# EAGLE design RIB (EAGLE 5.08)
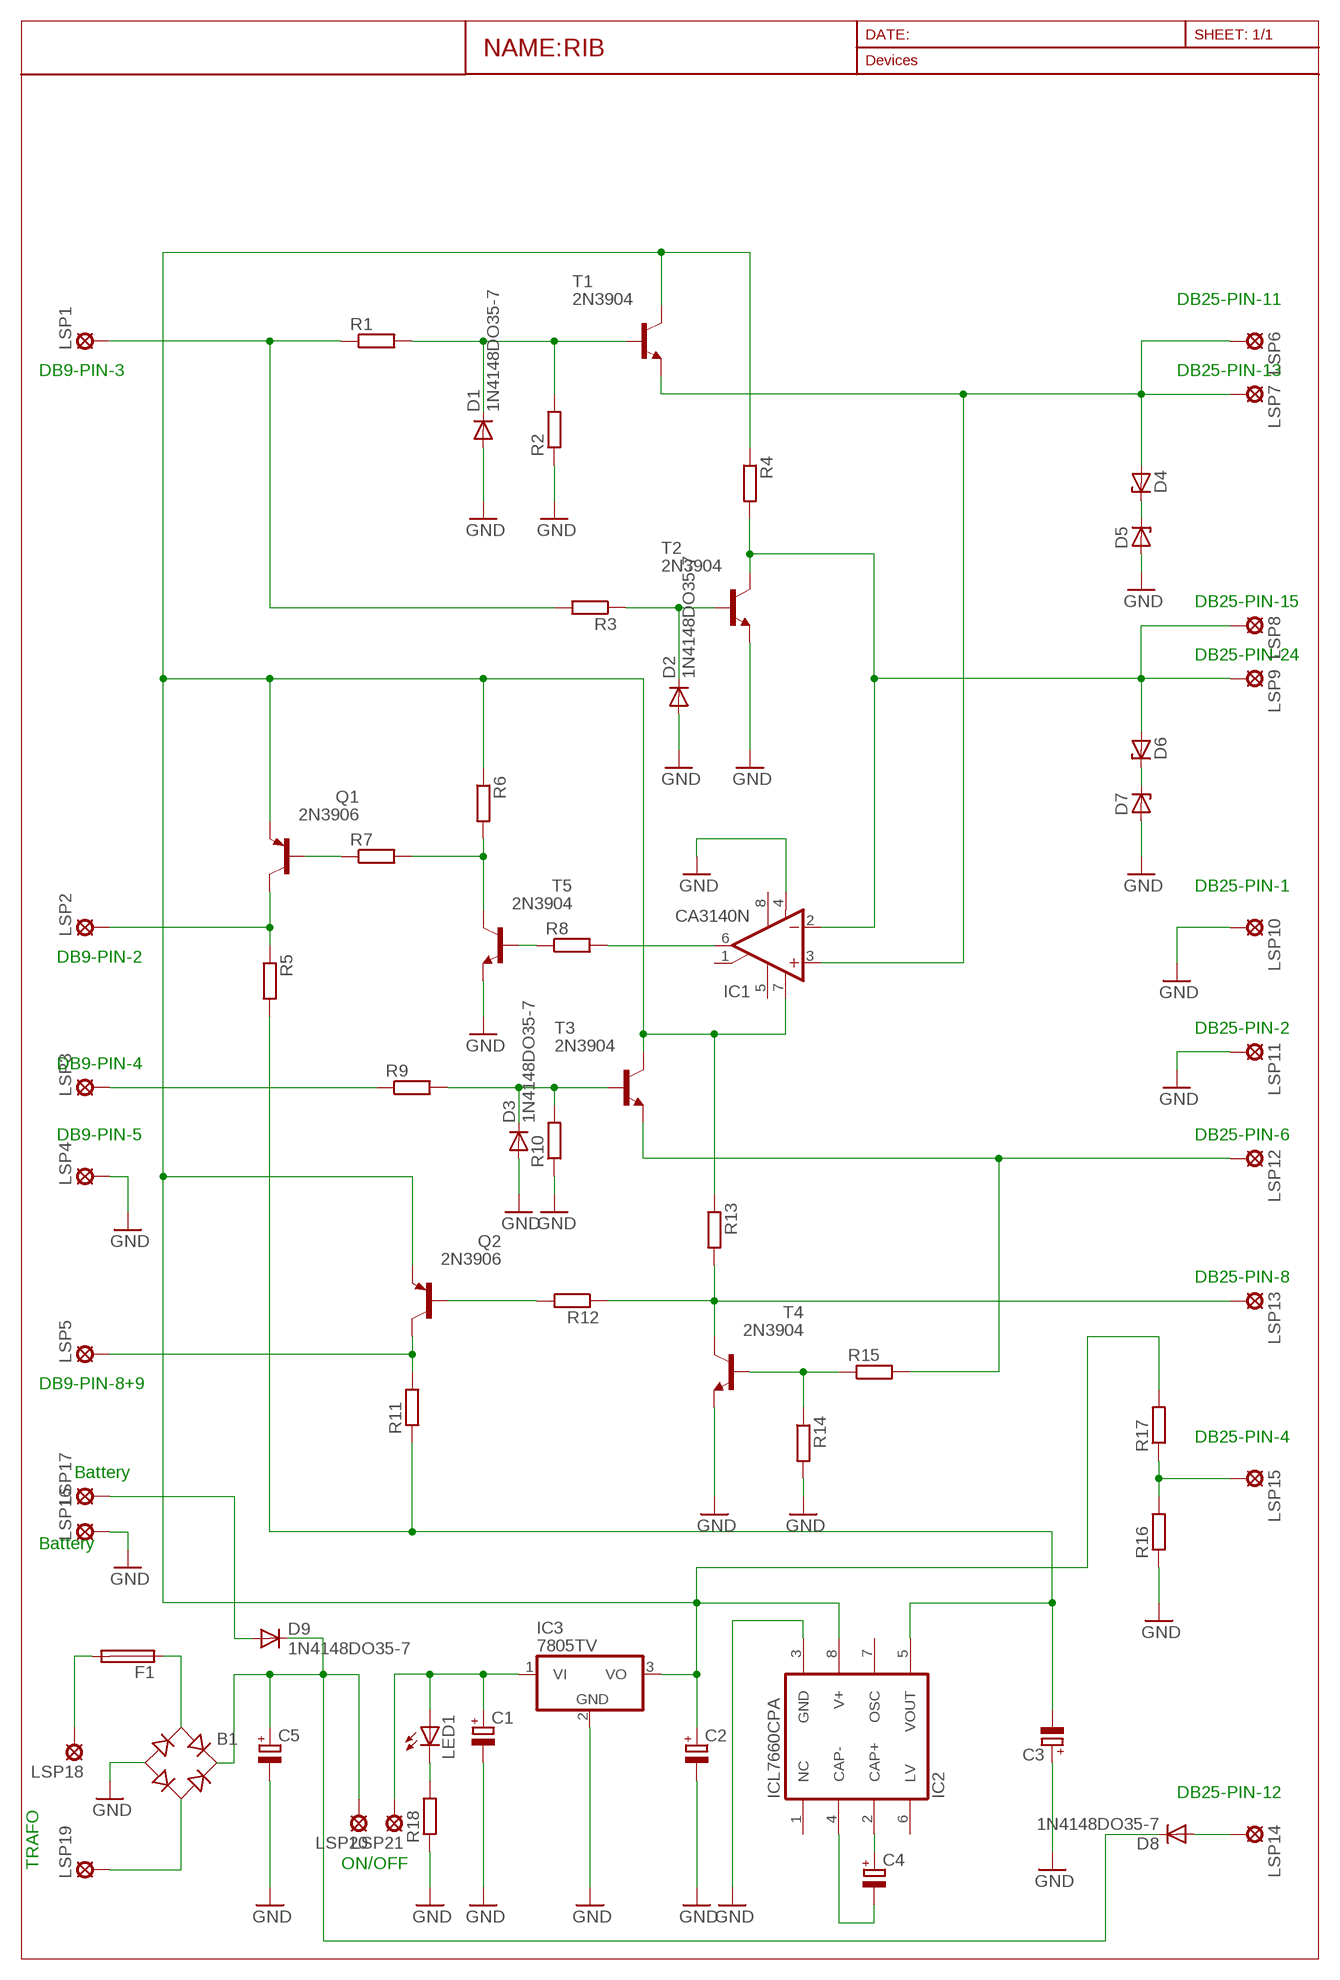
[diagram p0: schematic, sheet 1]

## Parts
B1  RB1A  [RB1A]
C1  CPOL-EUE2.5-6  [E2,5-6]
C2  CPOL-EUE2.5-6  [E2,5-6]
C3  CPOL-EUE2.5-6  [E2,5-6]
C4  CPOL-EUE2.5-6  [E2,5-6]
C5  CPOL-EUE3.5-10  [E3,5-10]
D1  1N4148DO35-7  [DO35-7]
D2  1N4148DO35-7  [DO35-7]
D3  1N4148DO35-7  [DO35-7]
D4  ZENER-DIODEZD-5  [ZDIO-5]
D5  ZENER-DIODEZD-5  [ZDIO-5]
D6  ZENER-DIODEZD-5  [ZDIO-5]
D7  ZENER-DIODEZD-5  [ZDIO-5]
D8  1N4148DO35-7  [DO35-7]
D9  1N4148DO35-7  [DO35-7]
F1  SH25  [SH25]
IC1  CA3140N  [DIL08]
IC2  ICL7660CPA  [DIL08]
IC3  7805TV  [TO220V]
LED1  LED5MM  [LED5MM]
LSP1  SE14  [SE14]
LSP2  SE14  [SE14]
LSP3  SE14  [SE14]
LSP4  SE14  [SE14]
LSP5  SE14  [SE14]
LSP6  SE14  [SE14]
LSP7  SE14  [SE14]
LSP8  SE14  [SE14]
LSP9  SE14  [SE14]
LSP10  SE14  [SE14]
LSP11  SE14  [SE14]
LSP12  SE14  [SE14]
LSP13  SE14  [SE14]
LSP14  SE14  [SE14]
LSP15  SE14  [SE14]
LSP16  SE14  [SE14]
LSP17  SE14  [SE14]
LSP18  SE14  [SE14]
LSP19  SE14  [SE14]
LSP20  SE14  [SE14]
LSP21  SE14  [SE14]
Q1  2N3906  [TO92]
Q2  2N3906  [TO92]
R1  R-EU_0204/7  [0204/7]
R2  R-EU_0204/7  [0204/7]
R3  R-EU_0204/7  [0204/7]
R4  R-EU_0204/7  [0204/7]
R5  R-EU_0204/7  [0204/7]
R6  R-EU_0204/7  [0204/7]
R7  R-EU_0204/7  [0204/7]
R8  R-EU_0204/7  [0204/7]
R9  R-EU_0204/7  [0204/7]
R10  R-EU_0204/7  [0204/7]
R11  R-EU_0204/7  [0204/7]
R12  R-EU_0204/7  [0204/7]
R13  R-EU_0204/7  [0204/7]
R14  R-EU_0204/7  [0204/7]
R15  R-EU_0204/7  [0204/7]
R16  R-EU_0204/7  [0204/7]
R17  R-EU_0204/7  [0204/7]
R18  R-EU_0204/7  [0204/7]
T1  2N3904  [TO92]
T2  2N3904  [TO92]
T3  2N3904  [TO92]
T4  2N3904  [TO92]
T5  2N3904  [TO92]

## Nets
GND: B1.- C1.- C2.- C3.+ C5.- D1.A D2.A D3.A D5.A D7.A IC1.4(V-) IC2.3(GND) IC3.2(GND) LSP4.MP LSP10.MP LSP11.MP LSP16.MP R2.1 R10.1 R14.2 R16.1 R18.1 T2.3(E) T4.3(E) T5.3(E)
N$1: D1.C R1.2 R2.2 T1.2(B)
N$2: D2.C R3.1 T2.2(B)
N$3: LSP3.MP R9.1
N$4: D4.C D5.C
N$5: D6.C D7.C
N$6: IC1.6(OUT) R8.2
N$7: R8.1 T5.2(B)
N$8: R6.2 R7.2 T5.1(C)
N$9: LSP2.MP Q1.1(C) R5.1
N$10: LSP1.MP R1.1 R3.2
N$11: D3.C R9.2 R10.2 T3.2(B)
N$12: LSP13.MP R12.1 R13.2 T4.1(C)
N$13: Q2.2(B) R12.2
N$14: LSP5.MP Q2.1(C) R11.2
N$15: R14.1 R15.1 T4.2(B)
N$16: LSP15.MP R16.2 R17.1
N$17: B1.+ C5.+ D8.C D9.C LSP20.MP
N$18: C2.+ IC1.7(V+) IC2.8(V+) IC3.3(VO) Q1.3(E) Q2.3(E) R4.1 R6.1 R13.1 R17.2 T1.1(C) T3.1(C)
N$19: C3.- IC2.5(VOUT) R5.2 R11.1
N$20: LSP12.MP R15.2 T3.3(E)
N$21: C4.+ IC2.2(CAP+)
N$22: C4.- IC2.4(CAP-)
N$23: F1.2 LSP18.MP
N$24: B1.AC2 LSP19.MP
N$25: D4.A IC1.3(+IN) LSP6.MP LSP7.MP T1.3(E)
N$26: D6.A IC1.2(-IN) LSP8.MP LSP9.MP R4.2 T2.1(C)
N$27: B1.AC1 F1.1
N$28: D8.A LSP14.MP
N$29: LED1.K(C) R18.2
N$30: Q1.2(B) R7.1
N$53: D9.A LSP17.MP
N$54: C1.+ IC3.1(VI) LED1.A LSP21.MP
Unconnected: IC1.1(ON/CMP) IC1.5(ON) IC1.8(CMP) IC2.1(NC) IC2.6(LV) IC2.7(OSC)

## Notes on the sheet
- DB25-PIN-11
- DB9-PIN-3 | DB25-PIN-13
- DB25-PIN-15
- DB25-PIN-24
- DB25-PIN-1
- DB9-PIN-2
- DB25-PIN-2
- DB9-PIN-4
- DB9-PIN-5 | DB25-PIN-6
- DB25-PIN-8
- DB9-PIN-8+9
- DB25-PIN-4
- Battery
- Battery
- DB25-PIN-12
- TRAFO | ON/OFF

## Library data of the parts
B1 = rectifier:RB1A: RECTIFIER 1 A
C1-C5 = rcl:CPOL-EU: POLARIZED CAPACITOR, European symbol
D1-D3 D8 D9 = diode:1N4148: DIODE
D4-D7 = diode:ZENER-DIODE: Z-Diode
F1 = fuse:SH25: FUSE HOLDER
IC1 = linear:CA3140: OP AMP
IC2 = maxim:ICL7660CPA: VOLTAGE CONVERTER
IC3 = linear:78*: Positive VOLTAGE REGULATOR Source: http://cache.national.com/ds/LM/LM78L05.pdf http://www.fairchildsemi.com/ds/LM/LM7805.pdf
LED1 = led:LED: LED
LSP1-LSP21 = solpad:SE14: SOLDER PAD
Q1 Q2 = transistor-pnp:2N3906: PNP Transistor
R1-R18 = rcl:R-EU_: RESISTOR, European symbol
T1-T5 = transistor:2N3904: NPN TRANSISTOR

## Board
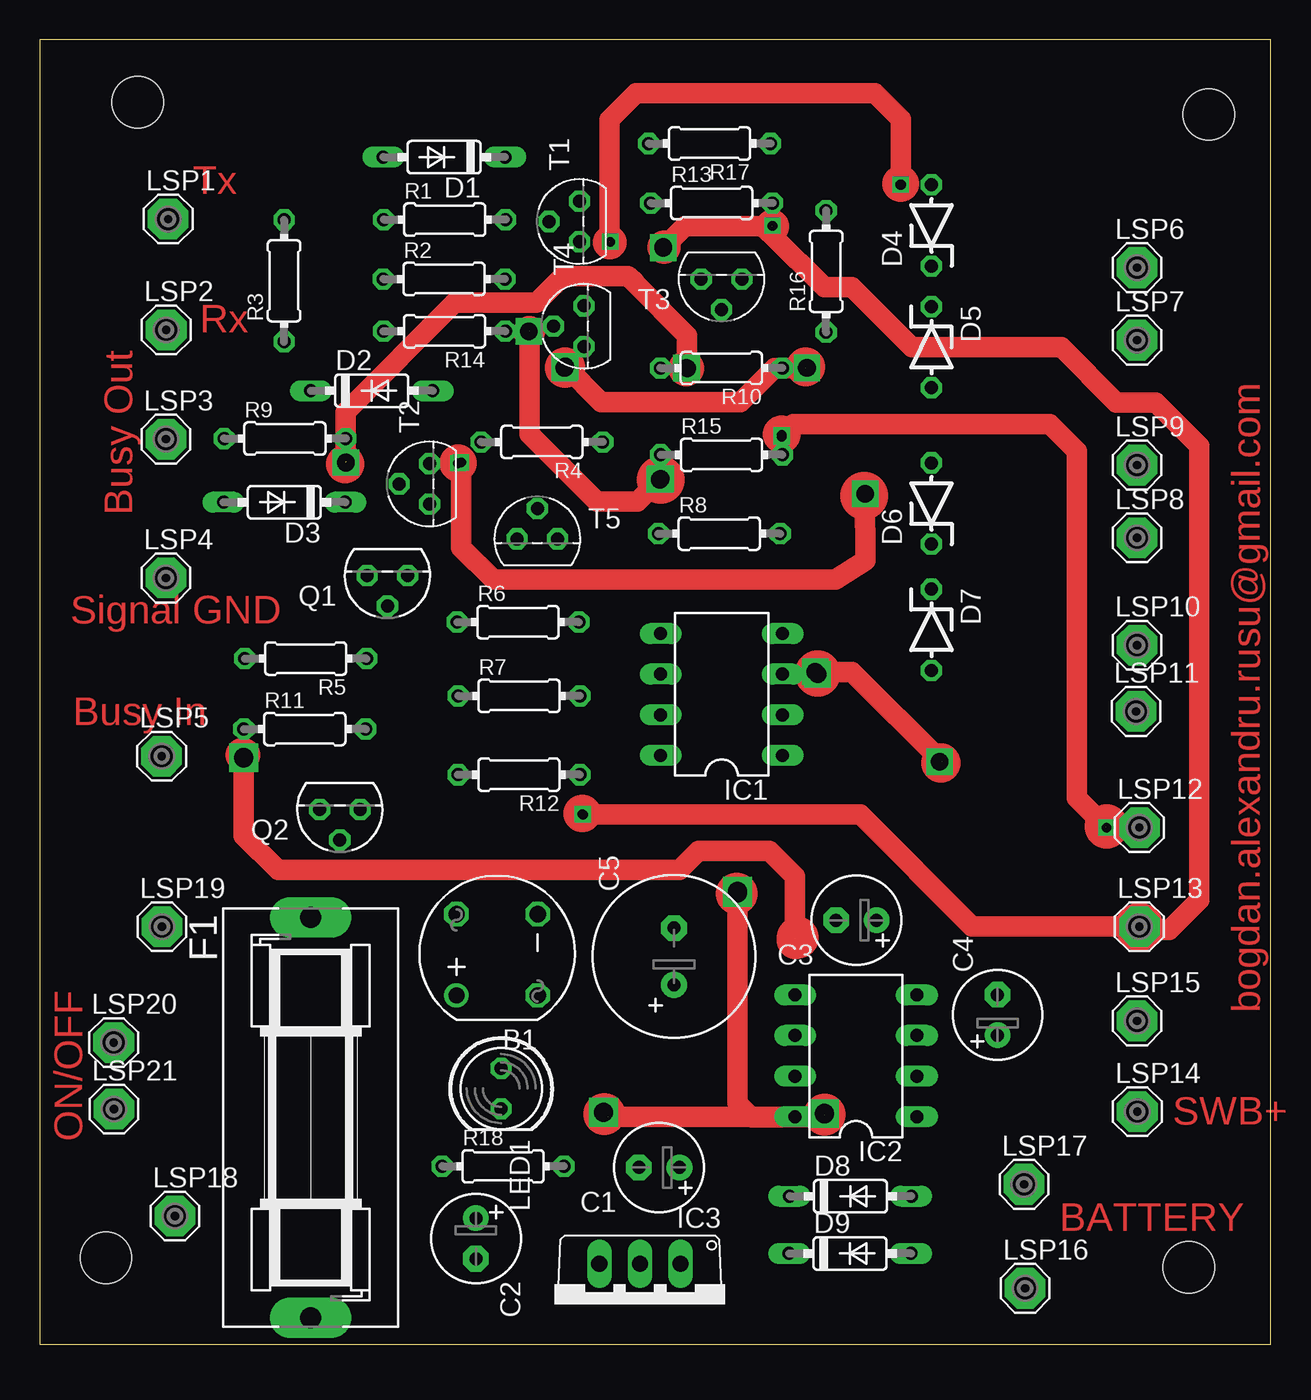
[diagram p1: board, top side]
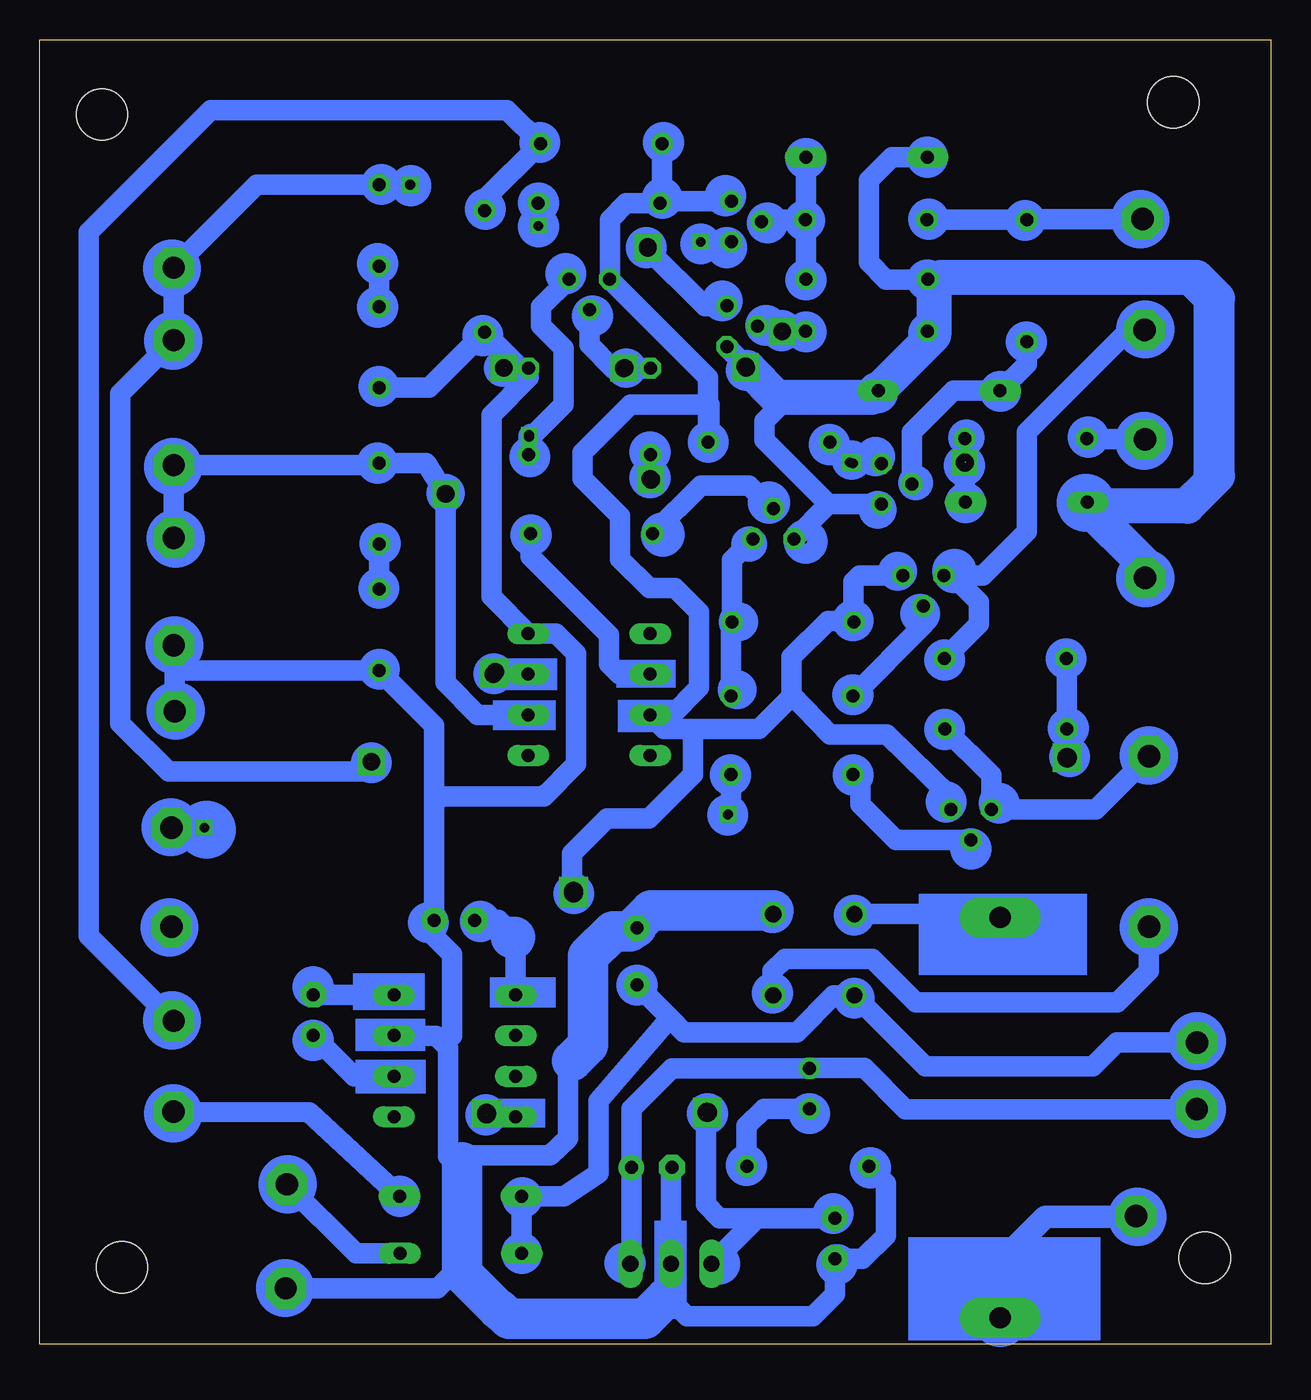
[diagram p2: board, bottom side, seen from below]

Size 76.99 x 81.59 mm. Coordinates in mm from the lower left corner, seen from the top.
Outline: 0,0 76.99,0 76.99,81.59 0,81.59 0,0
Copper layers (1*16): Top 0.035mm / dielectric 1.5mm / Bottom 0.035mm
Design rules "default": minimum track width 10mil, minimum drill 24mil, track to track 8mil, track to pad 8mil, pad to pad 8mil, via to via 8mil, smd to smd 8mil, copper to edge 40mil, drill to drill 8mil, minimum pad ring 10mil, minimum via ring 8mil, stop-mask expansion 4mil, vias tented up to drill 0mil, thermal gap 10mil
Holes 3.2 mm at 6.11,77.69 71.86,4.82 4.13,5.41 73.12,76.93

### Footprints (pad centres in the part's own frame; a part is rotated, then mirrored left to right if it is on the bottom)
RB1A = drill 1.016 round: + -2.54,2.54 | drill 1.016 octagon: - 2.54,-2.54; AC1 2.54,2.54; AC2 -2.54,-2.54
E2,5-6 = drill 0.813 pad 1.6 round: + -1.27,0 | drill 0.813 pad 1.6 octagon: - 1.27,0
E3,5-10 = drill 0.813 pad 1.6 round: + -1.778,0 | drill 0.813 pad 1.6 octagon: - 1.778,0
DO35-7 = drill 0.813 long: A 3.81,0; C -3.81,0
ZDIO-5 = drill 0.813 octagon: A 2.54,0; C -2.54,0
SH25 = drill 1.321 pad 2.54 long: 1 -12.522,0; 2 12.522,0
DIL08 = drill 0.813 long: 1 -3.81,-3.81; 2 -1.27,-3.81; 3 1.27,-3.81; 4 3.81,-3.81; 5 3.81,3.81; 6 1.27,3.81; 7 -1.27,3.81; 8 -3.81,3.81
TO220V = drill 1.016 long: 1 -2.54,-2.54; 2 0,-2.54; 3 2.54,-2.54
LED5MM = drill 0.813 octagon: A -1.27,0; K 1.27,0
SE14 = drill 1.397 pad 2.54 octagon: MP 0,0
TO92 = drill 0.813 octagon: 1 1.27,0; 2 0,1.905; 3 -1.27,0
0204/7 = drill 0.813 octagon: 1 -3.81,0; 2 3.81,0

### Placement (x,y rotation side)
B1  28.6,24.37 90 top
C1  38.73,11.06 180 top
C2  27.27,6.62 270 top
C3  51.07,26.53 180 top
C4  59.9,20.6 90 top
C5  39.66,24.26 90 top
D1  25.28,74.26 180 top
D2  20.75,59.65 0 top
D3  15.29,52.67 180 top
D4  55.77,69.99 90 top
D5  55.77,62.37 270 top
D6  55.77,52.6 90 top
D7  55.77,44.69 270 top
D8  50.7,9.26 0 top
D9  50.67,5.68 0 top
F1  16.93,14.19 270 top
IC1  42.64,40.65 90 top
IC2  51.04,18.04 90 top
IC3  37.53,2.49 180 top
LED1  28.85,16 270 top
LSP1  8.01,70.39 0 top
LSP2  7.9,63.46 0 top
LSP3  7.88,56.62 0 top
LSP4  7.88,47.94 0 top
LSP5  7.61,36.79 0 top
LSP6  68.63,67.35 0 top
LSP7  68.63,62.82 0 top
LSP8  68.63,50.45 0 top
LSP9  68.63,54.99 0 top
LSP10  68.63,43.73 0 top
LSP11  68.56,39.59 0 top
LSP12  68.77,32.32 0 top
LSP13  68.77,26.13 0 top
LSP14  68.64,14.55 0 top
LSP15  68.63,20.23 0 top
LSP16  61.63,3.5 0 top
LSP17  61.55,10.01 0 top
LSP18  8.44,8.02 0 top
LSP19  7.63,26.12 0 top
LSP20  4.61,18.88 0 top
LSP21  4.63,14.71 0 top
Q1  21.73,48.09 180 top
Q2  18.76,33.46 180 top
R1  25.32,70.35 0 top
R2  25.27,66.64 0 top
R3  15.27,66.52 90 top
R4  31.39,56.44 180 top
R5  16.62,42.89 180 top
R6  29.9,45.17 0 top
R7  29.97,40.56 0 top
R8  42.49,50.71 0 top
R9  15.32,56.66 0 top
R10  42.62,61.07 180 top
R11  16.57,38.49 0 top
R12  29.96,35.63 180 top
R13  42.01,71.39 0 top
R14  25.3,63.37 180 top
R15  42.63,55.64 0 top
R16  49.18,67.11 90 top
R17  41.88,75.11 180 top
R18  28.97,11.13 0 top
T1  33.76,70.24 90 top
T2  24.37,53.82 90 top
T3  42.63,66.64 180 top
T4  34.03,63.69 90 top
T5  31.11,50.38 0 top

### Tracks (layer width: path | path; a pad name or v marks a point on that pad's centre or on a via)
GND  (via drill 1.1)  (1 unrouted)
  Top 1.27: v32.86,61.17 35.1,58.94 43.83,58.94 45.96,61.07 47.87,61.07
  Bottom 1.27: R18.1 24.09,10.07 24.09,6.8 25.54,5.35 C2.- 27.27,3.14 28.66,1.75 36.51,1.75 37.58,2.83 | LSP4.MP 7.88,49.07 D3.A 5.69,52.67 4.2,54.16 4.2,65.25 5.63,66.69 21.41,66.69 R2.1 | 27.67,52.55 T5.3 | 27.67,52.55 T2.3 | 68.56,42.04 LSP11.MP | 68.56,42.04 68.56,43.67 LSP10.MP | D1.A 23.71,74.26 25.14,72.83 25.14,67.68 24.07,66.6 21.5,66.6 R2.1 | R2.1 21.47,63.4 R14.2 21.49,62.72 D2.A | D2.A 31.26,59.65 T4.3 34.03,62.34 v32.86,61.17 | D5.A 52.65,59.83 R16.1 46.94,61.07 R10.1 | R10.1 46.43,60.45 48.76,58.13 48.76,46.76 IC1.4 44.71,44.46 43.46,43.21 43.46,36.3 45.48,34.28 | 68.56,42.04 68.45,42.15 D7.A 52.34,38.72 52.34,33.85 | 52.34,33.85 C3.+ 52.34,25.52 51.22,24.4 51.22,19.28 51.72,18.78 | D2.A 29.78,59.65 31.67,57.76 31.67,56.55 27.67,52.55 | 45.48,34.28 51.9,34.28 52.34,33.85 | R10.1 47.87,61.07 47.92,61.01 | C1.- 37.53,11.06 IC3.2 37.58,4.98 37.58,2.83 | B1.- 38.79,26.91 C5.- 41.21,26.04 42.73,24.52 42.73,18.42 43.95,17.12 43.95,12.89 45.09,11.83 50.57,11.83 51.06,11.34 | 45.48,34.28 45.48,34.38 | LSP16.MP 52.12,3.5 51.22,4.4 | 51.22,4.4 51.06,4.56 51.06,11.34 | 51.06,11.34 51.47,11.76 51.47,18.53 51.72,18.78 | 51.72,18.78 52.21,19.28 54.82,19.28 IC2.3 | 37.58,2.83 37.58,2.33 38.25,1.67 48.49,1.67 51.22,4.4
N$1
  Bottom 1.27: D1.C 29.09,70.38 R1.2 | R1.2 31.74,70.35 T1.2 | R2.2 29.09,70.31 R1.2
N$2
  Bottom 1.27: R3.1 15.27,61.32 D2.C 19.87,59.65 22.46,57.06 T2.2
N$3
  Bottom 1.27: LSP3.MP 11.47,56.62 R9.1
N$4
  Bottom 1.27: D4.C D5.C
N$5
  Bottom 1.27: D7.C D6.C | D7.C
N$6
  Bottom 1.27: IC1.6 40.78,41.92 41.41,42.55 41.41,44.38 46.31,49.29 46.31,50.69 R8.2
N$7
  Bottom 1.27: R8.1 35.66,53.73 32.66,53.73 31.21,52.29 T5.2
N$8
  Bottom 1.27: T5.1 33.71,49.05 R6.2 33.78,45.11 R7.2
N$9
  Bottom 1.27: R5.1 18.27,45.05 18.27,46.43 19.93,48.09 Q1.1 18.01,48.09 15.27,50.83 15.27,57.05 9.15,63.17 8.18,63.17 LSP2.MP
N$10
  Bottom 1.27: LSP1.MP 15.22,70.39 R3.2 21.49,70.33 R1.1
N$11  (via drill 1.1)  (1 unrouted)
  Top 1.27: v40.48,61.05 40.48,63.1 37.21,66.37 37.21,66.41 36.79,66.83 32.73,66.83 31.05,65.15 25.94,65.15 19.11,58.32 19.11,55.18 19.07,55.14
  Bottom 1.27: R9.2 19.13,52.71 D3.C | T3.2 42.63,62.52 41.14,61.03 38.85,61.03 R10.2 | R9.2 19.13,55.22 19.19,55.16 | R10.2 40.05,61.07 40.15,60.96 | R9.2 19.07,56.6 19.07,55.06 | R10.2 38.83,61.05 v40.48,61.05
N$12  (via drill 0.6, 1.1)  (1 unrouted)
  Top 1.27: v33.97,33.13 51.31,33.13 58.3,26.15 68.21,26.15 | 68.21,26.15 68.75,26.15 LSP13.MP | 68.21,26.15 68.42,25.93 70.65,25.93 72.52,27.8 72.52,56.18 69.78,58.91 67.34,58.91 63.89,62.37 54.54,62.37 50.8,66.12 49.07,66.12 45.8,69.39 45.8,69.93 40.34,69.93 v38.98,68.57
  Bottom 1.27: R13.2 45.8,71.37 45.8,69.93 | T4.1 34.06,64.93 35.41,64.93 38.98,68.5 v38.98,68.57 | R12.1 33.77,33.33 v33.97,33.13
N$13
  Bottom 1.27: Q2.2 23.46,31.55 25.68,33.77 25.68,35.93 R12.2
N$14
  Bottom 1.27: LSP5.MP 10.94,33.46 Q2.1 17.49,35.6 R11.2
N$15  (via drill 1.1)  (1 unrouted)
  Top 1.27: v38.77,54.09 37.39,52.71 34.83,52.71 30.62,56.92 30.62,63.37
  Bottom 1.27: R14.1 30.62,63.37 | T4.2 31.81,63.37 30.62,63.37 | 30.62,63.37 30.58,63.41 | R15.1 38.82,54.14 v38.77,54.09
N$16
  Bottom 1.27: LSP15.MP 73.96,25.56 73.96,69.57 66.33,77.21 47.78,77.21 45.69,75.12 R17.1 49.18,71.63 R16.2
N$17
  Bottom 1.27: LSP20.MP 9.64,18.88 11.14,17.38 21.61,17.38 B1.+ 27.35,21.83 29.65,19.53 36.7,19.53 37.6,20.42 | 37.6,20.42 C5.+ | D9.C 46.86,9.24 D8.C 44.21,9.26 42.06,10.68 42.06,15.23 37.6,20.42
N$18  (via drill 1.2)  (2 unrouted)
  Top 1.27: v43.62,28.34 43.62,15.08 44.52,14.19 48.91,14.19 49.07,14.35 | IC2.8 35.54,14.23 35.26,14.52
  Bottom 1.27: C2.+ 32.13,7.89 | 32.13,7.89 IC3.3 | T1.1 38.09,71.51 R13.1 | R17.2 38.07,71.52 R13.1 | R13.1 40.32,71.39 41.35,70.36 T3.1 35.2,60.48 R4.1 35.12,56.52 35.12,58.77 40.06,58.77 43.07,55.77 43.07,54.16 40.71,51.8 40.71,49.12 38.88,47.29 37.27,47.29 35.77,45.79 35.77,41.07 37.59,39.25 37.59,38.49 | Q1.3 25.74,48.09 26.11,47.72 26.11,45.19 R6.1 26.17,45.25 27.72,45.25 29.97,43 29.97,40.64 | Q2.3 20.03,34.24 24.03,38.15 27.57,38.15 29.97,40.64 | IC1.7 37.95,38.49 37.59,38.49 | 36.16,38.49 32.01,38.49 29.97,40.53 29.97,40.64 | 36.16,38.49 37.59,38.49 | 36.16,38.49 36.15,38.5 36.15,35.65 38.91,32.89 41.51,32.89 43.71,30.7 43.71,28.42 v43.62,28.34 | IC2.8 48.95,14.23 49.07,14.35 | 32.13,7.89 34.48,7.89 35.34,8.74 35.34,14.03 35.54,14.23
N$19  (via drill 1.2)  (1 unrouted)
  Top 1.27: v12.74,36.69 12.74,31.81 14.89,29.66 39.99,29.66 41.19,30.85 45.63,30.85 47.21,29.28 47.21,25.42 47.23,25.4
  Bottom 1.27: IC2.5 47.23,25.47 48.31,26.54 49.79,26.54 C3.- | R5.2 12.76,42.84 R11.1 v12.76,36.7 v12.74,36.69
N$20  (via drill 0.6)  (1 unrouted)
  Top 1.27: v46.4,56.77 46.4,56.82 47.15,57.57 63.18,57.57 64.87,55.88 64.87,34.16 66.67,32.37
  Bottom 1.27: T3.3 45.64,64.89 45.64,63.71 44.25,62.31 44.25,58.77 46.44,56.58 R15.2 | R15.2 46.44,56.83 46.35,56.92 | LSP12.MP 66.71,32.32 66.67,32.37 | R15.2 46.44,56.73 v46.4,56.77
N$21
  Bottom 1.27: IC2.2 57.34,16.77 C4.+
N$22
  Bottom 1.27: IC2.4 59.88,21.85 C4.-
N$23
  Bottom 1.422: F1.2 16.93,5.15 14.11,7.97 8.49,7.97 LSP18.MP
N$24
  Bottom 1.27: LSP19.MP 7.63,23.37 9.61,21.39 22.19,21.39 24.93,24.12 30.39,24.12 31.17,23.35 31.17,21.86 B1.AC2
N$25  (via drill 0.6, 1.1)  (2 unrouted)
  Top 1.27: v53.86,72.54 53.86,76.63 52.24,78.25 37.29,78.25 35.64,76.6 35.64,68.97 | v48.5,42.06 50.79,42.06 56.41,36.44
  Bottom 1.27: LSP7.MP LSP6.MP 63.44,72.53 D4.A v53.86,72.53 v53.86,72.54 | LSP7.MP | T1.3 35.64,68.97 35.64,68.96 | IC1.3 48.36,41.92 v48.5,42.06 | LSP7.MP 71.97,59.48 71.97,38.85 68.94,35.82 57.04,35.82 arc-90 56.41,36.44 arc90 56.28,36.58
N$26  (via drill 0.6, 1.1)
  Top 1.27: v26.35,55.17 26.35,49.84 28.36,47.82 49.75,47.82 51.63,49.02 51.61,53.12 51.62,53.12 v51.62,53.19
  Bottom 1.27: T2.1 26.23,55.09 R4.2 26.35,55.21 v26.35,55.17 | LSP8.MP LSP9.MP 55.91,54.99 D6.A 55.75,55.12 52.83,55.12 v51.62,53.19 51.62,52.97 51.62,41.39 49.61,39.38 IC1.2
N$27
  Bottom 0.406: F1.1 21.73,26.71 21.73,26.91
  Bottom 1.27: 21.73,26.91 B1.AC1
N$28
  Bottom 1.27: LSP14.MP 60.15,14.5 D8.A
N$29
  Bottom 1.27: LED1.K 31.72,14.73 32.79,13.66 32.79,11.15 R18.2
N$30
  Bottom 1.27: Q1.2 21.73,44.99 R7.1
N$31  (via drill 1.2)
  other vias: 43.62,28.26
N$32  (via drill 1.2)
  other vias: 35.26,14.52
N$33  (via drill 0.6)
  other vias: 12.77,36.93
N$34  (via drill 0.6)
  other vias: 33.93,33.16
N$35  (via drill 0.6)
  other vias: 35.67,68.96
N$36  (via drill 0.6)
  other vias: 53.82,72.54
N$37  (via drill 0.6)
  other vias: 46.4,56.87
N$38  (via drill 0.6)
  other vias: 66.72,32.32
N$39  (via drill 0.6)
  other vias: 26.14,55.12
N$40  (via drill 0.6)
  other vias: 51.59,53.14
N$42  (via drill 0.6)
  other vias: 45.82,69.97
N$43  (via drill 1.1)
  other vias: 48.64,41.92
N$44  (via drill 1.1)
  other vias: 56.27,36.45
N$45  (via drill 1.1)
  other vias: 30.58,63.36
N$46  (via drill 1.1)
  other vias: 38.82,54.14
N$47  (via drill 1.1)
  other vias: 47.98,61.07
N$48  (via drill 1.1)
  other vias: 32.81,61.07
N$49  (via drill 1.1)
  other vias: 40.42,61.07
N$50  (via drill 1.1)
  other vias: 19.14,55.16
N$51  (via drill 1.1)
  other vias: 38.98,68.63
N$52
  Bottom 2.184: 7.96,48.1 7.96,48.83 11.56,52.43 5.22,52.43 3.34,54.31 3.34,65.44 4.64,66.73 20.65,66.73 21.08,66.3 21.08,63.12 24.98,59.22 30.89,59.22 32.62,60.96
N$53
  Bottom 1.27: D9.A 57.23,5.68 LSP17.MP
N$54
  Bottom 1.27: IC3.1 40,5.03 C1.+ 39.98,11.08 39.98,14.73 37.45,17.27 LED1.A 28.83,17.29 25.43,17.29 22.85,14.71 LSP21.MP
N$55  (via drill 1.2)
  other vias: 49.07,14.44
N$56
  Bottom 2.54: 31.11,27.15 38.77,27.15 40.08,25.84 41.16,25.84 42.71,24.29 42.71,18.73 43.71,17.73
N$57
  Bottom 2.54: 50.59,11.4 50.59,4.45 48.35,2.21 48.27,2.21 47.66,1.59 39.15,1.59 37.84,2.9
(copper drawn outside any net)
  shapes: Bottom area x12, Bottom circle x154, Top circle x26

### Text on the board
Top: Tx | Rx | bogdan.alexandru.rusu@gmail.com | Busy Out | Signal GND | Busy In | SWB+ | ON/OFF | BATTERY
